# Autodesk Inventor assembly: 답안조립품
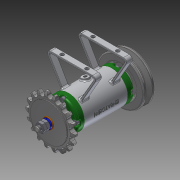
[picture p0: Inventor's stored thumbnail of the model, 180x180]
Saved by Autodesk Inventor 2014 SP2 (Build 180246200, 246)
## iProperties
Created: 2016-03
Part Number: 답안조립품
Document SubType Name: Assembly
Designer: 703
Author: 703
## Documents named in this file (12)
- C:\Users\703\Desktop\460307V1020\답안조립품.iam
- C:\Users\703\Desktop\460307V1020\본체.ipt
- C:\Users\703\Desktop\460307V1020\커버.ipt
- C:\Users\703\Desktop\460307V1020\베어링 15 x 32 x 9.ipt
- C:\Users\703\Desktop\460307V1020\축.ipt
- C:\Users\703\Desktop\460307V1020\볼트 M4 x 12.ipt
- C:\Users\703\Desktop\460307V1020\키 3 x 3 x 12.ipt
- C:\Users\703\Desktop\460307V1020\스프로킷.ipt
- C:\Users\703\Desktop\460307V1020\V벨트풀리.ipt
- C:\Users\703\Desktop\460307V1020\와셔 8x17.ipt
- C:\Users\703\Desktop\460307V1020\스프링와셔 8.ipt
- C:\Users\703\Desktop\460307V1020\너트 M 8.ipt
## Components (11 placed, 3 different names)
1. KS B 2023 6002 - 15 x 32 x 9:1
2. KS B 2023 6002 - 15 x 32 x 9:2
3. V벨트풀리:1
4. ISO 4762 M4 x 12:1
5. ISO 4762 M4 x 12:2
6. ISO 4762 M4 x 12:3
7. ISO 4762 M4 x 12:4
8. ISO 4762 M4 x 12:5
9. ISO 4762 M4 x 12:6
10. ISO 4762 M4 x 12:7
11. ISO 4762 M4 x 12:8
